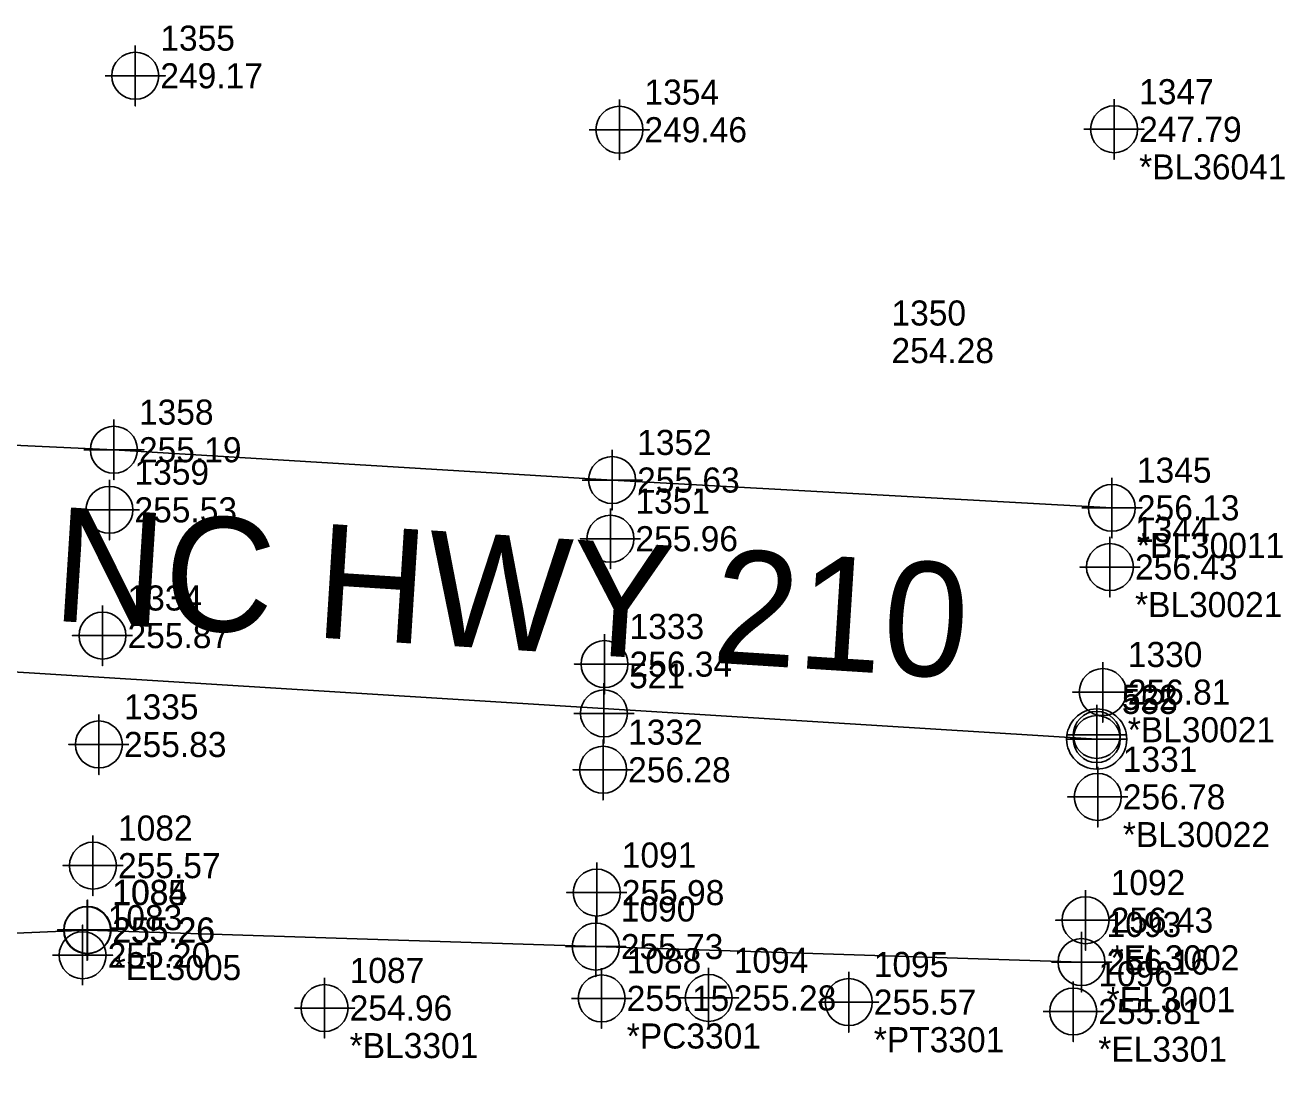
# Model space of a CAD drawing. Extents: x 2130621 to 2131998, y 642516 to 644503.
# Drawn here: x 2131338.9 to 2131464.5, y 643131.5 to 643237.6 of the extents above; entities that cross this region are included whole.
import ezdxf

# ---------------------------------------------------------------- set-up
doc = ezdxf.new("R2010")
doc.units = 0
for name, color, linetype in [('Cogo Default Point CELL', 7, 'Continuous'), ('COGO Default Point Number', 7, 'Continuous'), ('Exist Guardrail Cogo Comment', 7, 'Continuous'), ('Exist Guardrail Cogo Elevation', 7, 'Continuous'), ('Exist Guardrail Cogo Number', 7, 'Continuous'), ('Exist Guardrail Cogo Point CELL', 7, 'Continuous'), ('Exist Other Culture Sign Cogo Elevation', 7, 'Continuous'), ('Exist Other Culture Sign Cogo Number', 7, 'Continuous'), ('Exist Roads EOP', 7, 'Continuous'), ('Exist Roads EOP Cogo Comment', 7, 'Continuous'), ('Exist Roads EOP Cogo Elevation', 7, 'Continuous'), ('Exist Roads EOP Cogo Number', 7, 'Continuous'), ('Exist Roads EOP Cogo Point CELL', 7, 'Continuous'), ('Exist Roads EOT Cogo Comment', 7, 'Continuous'), ('Exist Roads EOT Cogo Elevation', 7, 'Continuous'), ('Exist Roads EOT Cogo Number', 7, 'Continuous'), ('Exist Roads EOT Cogo Point CELL', 7, 'Continuous'), ('Exist Roads EOT Text', 7, 'Continuous'), ('Exist Roads Soil Cogo Comment', 7, 'Continuous'), ('Exist Roads Soil Cogo Elevation', 7, 'Continuous'), ('Exist Roads Soil Cogo Number', 7, 'Continuous'), ('Exist Roads Soil Cogo Point CELL', 7, 'Continuous'), ('Exist Vegetation Woods Line Cogo Comment', 7, 'Continuous'), ('Exist Vegetation Woods Line Cogo Elevation', 7, 'Continuous'), ('Exist Vegetation Woods Line Cogo Number', 7, 'Continuous'), ('Exist Vegetation Woods Line Cogo Point CELL', 7, 'Continuous'), ('Prop Horizontal Alignment', 7, 'Continuous')]:
    doc.layers.add(name, color=color, linetype=linetype)

msp = doc.modelspace()

# ---------------------------------------------------------------- linework, layer by layer
at = {"layer": 'Cogo Default Point CELL'}
for points in [[(2131396.59, 643172.04), (2131396.59, 643169.04)], [(2131445.73, 643169.48), (2131445.73, 643166.48)], [(2131445.73, 643169.89), (2131445.73, 643166.89)], [(2131393.59, 643169.04), (2131396.59, 643169.04)], [(2131396.59, 643169.04), (2131399.59, 643169.04)], [(2131396.59, 643169.04), (2131396.59, 643166.04)], [(2131442.73, 643166.89), (2131445.73, 643166.89)], [(2131445.73, 643166.89), (2131448.73, 643166.89)], [(2131445.73, 643166.89), (2131445.73, 643163.89)], [(2131442.73, 643166.48), (2131445.73, 643166.48)], [(2131445.73, 643166.48), (2131448.73, 643166.48)], [(2131445.73, 643166.48), (2131445.73, 643163.48)]]:
    msp.add_lwpolyline(points, dxfattribs=at)
for centre in [(2131396.59, 643169.04), (2131445.73, 643166.89), (2131445.73, 643166.48)]:
    msp.add_circle(centre, 2.34, dxfattribs=at)
at = {"layer": 'Exist Guardrail Cogo Point CELL'}
for points in [[(2131396.36, 643143.63), (2131396.36, 643137.63), (2131396.36, 643140.63), (2131399.36, 643140.63), (2131393.36, 643140.63)], [(2131407.03, 643143.67), (2131407.03, 643137.67), (2131407.03, 643140.67), (2131410.03, 643140.67), (2131404.03, 643140.67)], [(2131421, 643143.26), (2131421, 643137.26), (2131421, 643140.26), (2131424, 643140.26), (2131418, 643140.26)], [(2131368.73, 643142.67), (2131368.73, 643136.67), (2131368.73, 643139.67), (2131371.73, 643139.67), (2131365.73, 643139.67)], [(2131443.39, 643142.32), (2131443.39, 643136.32), (2131443.39, 643139.32), (2131446.39, 643139.32), (2131440.39, 643139.32)]]:
    msp.add_lwpolyline(points, dxfattribs=at)
for centre in [(2131396.36, 643140.63), (2131407.03, 643140.67), (2131368.73, 643139.67), (2131421, 643140.26), (2131443.39, 643139.32)]:
    msp.add_circle(centre, 2.34, dxfattribs=at)
at = {"layer": 'Exist Roads EOP'}
for points in [[(2131447.24, 643189.53), (2131397.4, 643192.3), (2131347.72, 643195.32), (2131298.37, 643197.61), (2131274.58, 643203.53)], [(2131280.81, 643131.52), (2131296.96, 643145.39), (2131345.05, 643147.42), (2131395.77, 643145.79), (2131444.21, 643144.25)]]:
    msp.add_lwpolyline(points, dxfattribs=at)
at = {"layer": 'Exist Roads EOP Cogo Point CELL'}
for points in [[(2131347.72, 643198.32), (2131347.72, 643192.32), (2131347.72, 643195.32), (2131350.72, 643195.32), (2131344.72, 643195.32)], [(2131397.4, 643195.3), (2131397.4, 643189.3), (2131397.4, 643192.3), (2131400.4, 643192.3), (2131394.4, 643192.3)], [(2131447.24, 643192.53), (2131447.24, 643186.53), (2131447.24, 643189.53), (2131450.24, 643189.53), (2131444.24, 643189.53)], [(2131345.05, 643150.42), (2131345.05, 643144.42), (2131345.05, 643147.42), (2131348.05, 643147.42), (2131342.05, 643147.42)], [(2131395.77, 643148.79), (2131395.77, 643142.79), (2131395.77, 643145.79), (2131398.77, 643145.79), (2131392.77, 643145.79)], [(2131444.21, 643147.25), (2131444.21, 643141.25), (2131444.21, 643144.25), (2131447.21, 643144.25), (2131441.21, 643144.25)]]:
    msp.add_lwpolyline(points, dxfattribs=at)
for centre in [(2131347.72, 643195.32), (2131397.4, 643192.3), (2131447.24, 643189.53), (2131345.05, 643147.42), (2131395.77, 643145.79), (2131444.21, 643144.25)]:
    msp.add_circle(centre, 2.34, dxfattribs=at)
at = {"layer": 'Exist Roads EOT Cogo Point CELL'}
for points in [[(2131347.27, 643192.33), (2131347.27, 643186.33), (2131347.27, 643189.33), (2131344.27, 643189.33), (2131350.27, 643189.33)], [(2131397.23, 643189.45), (2131397.23, 643183.45), (2131397.23, 643186.45), (2131394.23, 643186.45), (2131400.23, 643186.45)], [(2131447.05, 643186.63), (2131447.05, 643180.63), (2131447.05, 643183.63), (2131444.05, 643183.63), (2131450.05, 643183.63)], [(2131346.58, 643179.79), (2131346.58, 643173.79), (2131346.58, 643176.79), (2131343.58, 643176.79), (2131349.58, 643176.79)], [(2131396.64, 643176.95), (2131396.64, 643170.95), (2131396.64, 643173.95), (2131393.64, 643173.95), (2131399.64, 643173.95)], [(2131446.33, 643174.16), (2131446.33, 643168.16), (2131446.33, 643171.16), (2131443.33, 643171.16), (2131449.33, 643171.16)], [(2131346.22, 643168.94), (2131346.22, 643162.94), (2131346.22, 643165.94), (2131343.22, 643165.94), (2131349.22, 643165.94)], [(2131396.5, 643166.42), (2131396.5, 643160.42), (2131396.5, 643163.42), (2131393.5, 643163.42), (2131399.5, 643163.42)], [(2131445.83, 643163.71), (2131445.83, 643157.71), (2131445.83, 643160.71), (2131442.83, 643160.71), (2131448.83, 643160.71)], [(2131345.63, 643156.86), (2131345.63, 643150.86), (2131345.63, 643153.86), (2131342.63, 643153.86), (2131348.63, 643153.86)], [(2131395.87, 643154.17), (2131395.87, 643148.17), (2131395.87, 643151.17), (2131392.87, 643151.17), (2131398.87, 643151.17)], [(2131444.62, 643151.42), (2131444.62, 643145.42), (2131444.62, 643148.42), (2131441.62, 643148.42), (2131447.62, 643148.42)]]:
    msp.add_lwpolyline(points, dxfattribs=at)
for centre in [(2131347.27, 643189.33), (2131397.23, 643186.45), (2131447.05, 643183.63), (2131346.58, 643176.79), (2131396.64, 643173.95), (2131446.33, 643171.16), (2131346.22, 643165.94), (2131396.5, 643163.42), (2131445.83, 643160.71), (2131345.63, 643153.86), (2131395.87, 643151.17), (2131444.62, 643148.42)]:
    msp.add_circle(centre, 2.34, dxfattribs=at)
at = {"layer": 'Exist Roads Soil Cogo Point CELL'}
for points in [[(2131345.09, 643144.45), (2131345.09, 643150.45), (2131345.09, 643147.45), (2131348.09, 643147.45), (2131342.09, 643147.45)], [(2131344.6, 643141.93), (2131344.6, 643147.93), (2131344.6, 643144.93), (2131347.6, 643144.93), (2131341.6, 643144.93)]]:
    msp.add_lwpolyline(points, dxfattribs=at)
for centre in [(2131345.09, 643147.45), (2131344.6, 643144.93)]:
    msp.add_circle(centre, 2.34, dxfattribs=at)
at = {"layer": 'Exist Vegetation Woods Line Cogo Point CELL'}
for points in [[(2131349.85, 643235.6), (2131349.85, 643229.6), (2131349.85, 643232.6), (2131352.85, 643232.6), (2131346.85, 643232.6)], [(2131398.13, 643230.22), (2131398.13, 643224.22), (2131398.13, 643227.22), (2131401.13, 643227.22), (2131395.13, 643227.22)], [(2131447.46, 643230.26), (2131447.46, 643224.26), (2131447.46, 643227.26), (2131450.46, 643227.26), (2131444.46, 643227.26)]]:
    msp.add_lwpolyline(points, dxfattribs=at)
for centre in [(2131349.85, 643232.6), (2131398.13, 643227.22), (2131447.46, 643227.26)]:
    msp.add_circle(centre, 2.34, dxfattribs=at)
at = {"layer": 'Prop Horizontal Alignment'}
msp.add_line((2131251.47, 643178.51), (2131445.73, 643166.48), dxfattribs=at)
msp.add_circle((2131445.73, 643166.48), 3, dxfattribs=at)

# ---------------------------------------------------------------- texts
at = {"layer": 'COGO Default Point Number'}
for s, p in [('521', (2131399.09, 643171.54)), ('522', (2131448.23, 643169.39)), ('555', (2131448.23, 643168.98))]:
    msp.add_text(s, height=2.5, dxfattribs=at).set_placement(p)
at = {"layer": 'Exist Guardrail Cogo Comment'}
for s, p in [('*PC3301', (2131398.86, 643135.63)), ('*BL3301', (2131371.23, 643134.67)), ('*PT3301', (2131423.5, 643135.26)), ('*EL3301', (2131445.89, 643134.32))]:
    msp.add_text(s, height=2.5, dxfattribs=at).set_placement(p)
at = {"layer": 'Exist Guardrail Cogo Elevation'}
for s, p in [('255.15', (2131398.86, 643139.38)), ('255.28', (2131409.53, 643139.42)), ('254.96', (2131371.23, 643138.42)), ('255.57', (2131423.5, 643139.01)), ('255.81', (2131445.89, 643138.07))]:
    msp.add_text(s, height=2.5, dxfattribs=at).set_placement(p)
at = {"layer": 'Exist Guardrail Cogo Number'}
for s, p in [('1088', (2131398.86, 643143.13)), ('1094', (2131409.53, 643143.17)), ('1087', (2131371.23, 643142.17)), ('1095', (2131423.5, 643142.76)), ('1096', (2131445.89, 643141.82))]:
    msp.add_text(s, height=2.5, dxfattribs=at).set_placement(p)
at = {"layer": 'Exist Other Culture Sign Cogo Elevation'}
msp.add_text('254.28', height=2.5, dxfattribs=at).set_placement((2131425.26, 643203.95))
at = {"layer": 'Exist Other Culture Sign Cogo Number'}
msp.add_text('1350', height=2.5, dxfattribs=at).set_placement((2131425.26, 643207.7))
at = {"layer": 'Exist Roads EOP Cogo Comment'}
for s, p in [('*BL30011', (2131449.74, 643184.53)), ('*EL3001', (2131446.71, 643139.25))]:
    msp.add_text(s, height=2.5, dxfattribs=at).set_placement(p)
at = {"layer": 'Exist Roads EOP Cogo Elevation'}
for s, p in [('255.19', (2131350.22, 643194.07)), ('255.63', (2131399.9, 643191.05)), ('256.13', (2131449.74, 643188.28)), ('255.26', (2131347.55, 643146.17)), ('255.73', (2131398.27, 643144.54)), ('256.16', (2131446.71, 643143))]:
    msp.add_text(s, height=2.5, dxfattribs=at).set_placement(p)
at = {"layer": 'Exist Roads EOP Cogo Number'}
for s, p in [('1358', (2131350.22, 643197.82)), ('1352', (2131399.9, 643194.8)), ('1345', (2131449.74, 643192.03)), ('1085', (2131347.55, 643149.92)), ('1090', (2131398.27, 643148.29)), ('1093', (2131446.71, 643146.75))]:
    msp.add_text(s, height=2.5, dxfattribs=at).set_placement(p)
at = {"layer": 'Exist Roads EOT Cogo Comment'}
for s, p in [('*BL30021', (2131449.55, 643178.63)), ('*BL30021', (2131448.83, 643166.16)), ('*BL30022', (2131448.33, 643155.71)), ('*EL3002', (2131447.12, 643143.42))]:
    msp.add_text(s, height=2.5, dxfattribs=at).set_placement(p)
at = {"layer": 'Exist Roads EOT Cogo Elevation'}
for s, p in [('255.53', (2131349.77, 643188.08)), ('255.96', (2131399.73, 643185.2)), ('256.43', (2131449.55, 643182.38)), ('255.87', (2131349.08, 643175.54)), ('256.34', (2131399.14, 643172.7)), ('256.81', (2131448.83, 643169.91)), ('255.83', (2131348.72, 643164.69)), ('256.28', (2131399, 643162.17)), ('256.78', (2131448.33, 643159.46)), ('255.57', (2131348.13, 643152.61)), ('255.98', (2131398.37, 643149.92)), ('256.43', (2131447.12, 643147.17))]:
    msp.add_text(s, height=2.5, dxfattribs=at).set_placement(p)
at = {"layer": 'Exist Roads EOT Cogo Number'}
for s, p in [('1359', (2131349.77, 643191.83)), ('1351', (2131399.73, 643188.95)), ('1344', (2131449.55, 643186.13)), ('1334', (2131349.08, 643179.29)), ('1333', (2131399.14, 643176.45)), ('1330', (2131448.83, 643173.66)), ('1335', (2131348.72, 643168.44)), ('1332', (2131399, 643165.92)), ('1331', (2131448.33, 643163.21)), ('1082', (2131348.13, 643156.36)), ('1091', (2131398.37, 643153.67)), ('1092', (2131447.12, 643150.92))]:
    msp.add_text(s, height=2.5, dxfattribs=at).set_placement(p)
at = {"layer": 'Exist Roads EOT Text'}
msp.add_text('NC HWY 210 ', height=11.3735, rotation=356.3624, dxfattribs=at).set_placement((2131341.47, 643178.29))
at = {"layer": 'Exist Roads Soil Cogo Comment'}
msp.add_text('*EL3005', height=2.5, dxfattribs=at).set_placement((2131347.59, 643142.45))
at = {"layer": 'Exist Roads Soil Cogo Elevation'}
for s, p in [('255.26', (2131347.59, 643146.2)), ('255.20', (2131347.1, 643143.68))]:
    msp.add_text(s, height=2.5, dxfattribs=at).set_placement(p)
at = {"layer": 'Exist Roads Soil Cogo Number'}
for s, p in [('1084', (2131347.59, 643149.95)), ('1083', (2131347.1, 643147.43))]:
    msp.add_text(s, height=2.5, dxfattribs=at).set_placement(p)
at = {"layer": 'Exist Vegetation Woods Line Cogo Comment'}
msp.add_text('*BL36041', height=2.5, dxfattribs=at).set_placement((2131449.96, 643222.26))
at = {"layer": 'Exist Vegetation Woods Line Cogo Elevation'}
for s, p in [('249.17', (2131352.35, 643231.35)), ('249.46', (2131400.63, 643225.97)), ('247.79', (2131449.96, 643226.01))]:
    msp.add_text(s, height=2.5, dxfattribs=at).set_placement(p)
at = {"layer": 'Exist Vegetation Woods Line Cogo Number'}
for s, p in [('1355', (2131352.35, 643235.1)), ('1354', (2131400.63, 643229.72)), ('1347', (2131449.96, 643229.76))]:
    msp.add_text(s, height=2.5, dxfattribs=at).set_placement(p)

doc.saveas('drawing.dxf')
